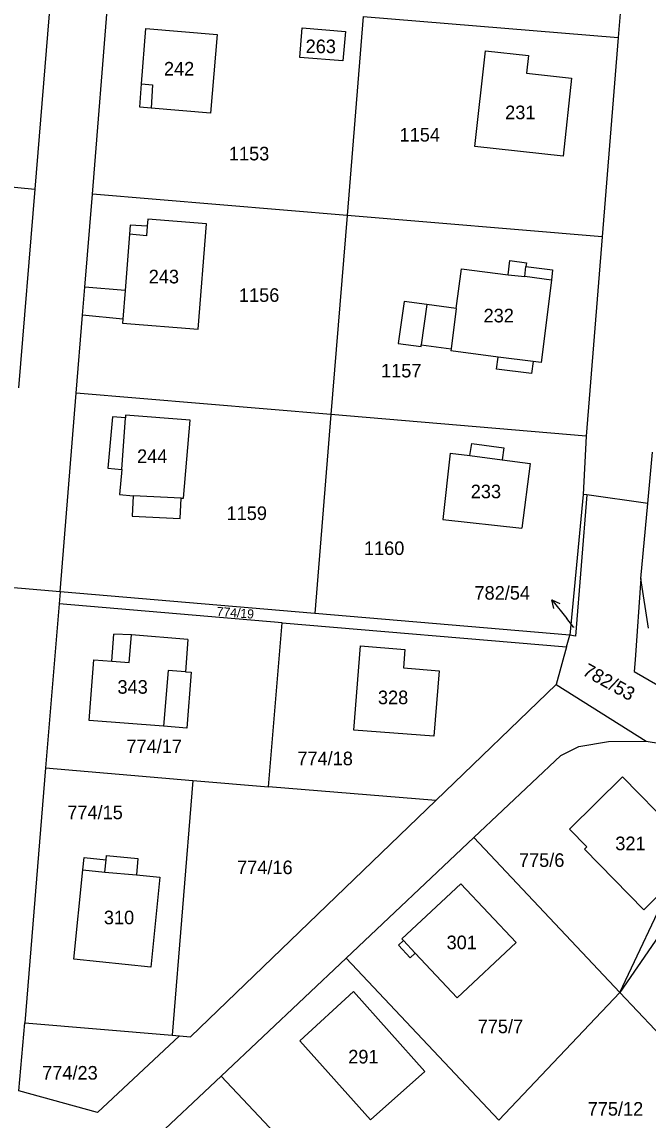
# Model space of a CAD drawing. Extents: x -593358 to -590116, y -1072518 to -1068420.
# Drawn here: x -591943 to -591864.7, y -1070840.2 to -1070702.8 of the extents above; entities that cross this region are included whole.
import ezdxf

# ---------------------------------------------------------------- set-up
doc = ezdxf.new("R2010")
doc.units = 0
for name, color, linetype in [('Parcela KN', 7, 'Continuous'), ('Parcelní číslo', 7, 'Continuous'), ('Parcelní číslo_stavební', 7, 'Continuous'), ('stavby - vnitřní kresba', 7, 'Continuous'), ('Vrstva 16', 7, 'Continuous')]:
    doc.layers.add(name, color=color, linetype=linetype)

msp = doc.modelspace()

# ---------------------------------------------------------------- linework, layer by layer
at = {"layer": 'Parcela KN'}
for p, q in [((-591866.36, -1070679.78), (-591868.38, -1070704.72)), ((-591939.39, -1070698.87), (-591941.43, -1070723.73)), ((-591934.22, -1070724.35), (-591932.21, -1070699.47)), ((-591900.32, -1070702.09), (-591902.34, -1070727)), ((-591900.32, -1070702.09), (-591868.38, -1070704.72)), ((-591928.05, -1070710.51), (-591927.51, -1070703.6)), ((-591927.51, -1070703.6), (-591918.61, -1070704.34)), ((-591918.61, -1070704.34), (-591919.43, -1070714.2)), ((-591908.26, -1070707.25), (-591907.94, -1070703.51)), ((-591907.94, -1070703.51), (-591902.53, -1070703.98)), ((-591902.53, -1070703.98), (-591902.85, -1070707.64)), ((-591868.38, -1070704.72), (-591870.4, -1070729.66)), ((-591902.85, -1070707.64), (-591908.26, -1070707.25)), ((-591886.34, -1070718.35), (-591885.01, -1070706.4)), ((-591885.01, -1070706.4), (-591879.63, -1070707)), ((-591879.63, -1070707), (-591879.88, -1070709.2)), ((-591879.88, -1070709.2), (-591874.23, -1070709.83)), ((-591874.23, -1070709.83), (-591875.29, -1070719.6)), ((-591928.28, -1070713.46), (-591928.05, -1070710.51)), ((-591926.87, -1070713.58), (-591928.28, -1070713.46)), ((-591919.43, -1070714.2), (-591926.87, -1070713.58)), ((-591875.29, -1070719.6), (-591886.34, -1070718.35)), ((-591973.3, -1070720.57), (-591941.43, -1070723.73)), ((-591941.43, -1070723.73), (-591943.47, -1070748.59)), ((-591935.16, -1070735.96), (-591934.22, -1070724.35)), ((-591902.34, -1070727), (-591934.22, -1070724.35)), ((-591927.29, -1070727.47), (-591927.36, -1070728.35)), ((-591919.92, -1070728.06), (-591927.29, -1070727.47)), ((-591920.97, -1070741.24), (-591919.92, -1070728.06)), ((-591902.34, -1070727), (-591904.37, -1070751.91)), ((-591870.4, -1070729.66), (-591902.34, -1070727)), ((-591929.57, -1070729.36), (-591930.13, -1070736.4)), ((-591929.48, -1070728.2), (-591929.57, -1070729.36)), ((-591927.36, -1070728.35), (-591929.48, -1070728.2)), ((-591870.4, -1070729.66), (-591872.42, -1070754.6)), ((-591882.18, -1070734.45), (-591881.95, -1070732.64)), ((-591881.95, -1070732.64), (-591879.89, -1070732.91)), ((-591879.89, -1070732.91), (-591879.95, -1070733.4)), ((-591879.95, -1070733.4), (-591876.6, -1070733.81)), ((-591888.66, -1070738.66), (-591888.02, -1070733.69)), ((-591888.02, -1070733.69), (-591882.18, -1070734.45)), ((-591876.6, -1070733.81), (-591876.76, -1070735.11)), ((-591935.44, -1070739.46), (-591935.16, -1070735.96)), ((-591930.13, -1070736.4), (-591935.16, -1070735.96)), ((-591876.76, -1070735.11), (-591878.06, -1070745.41)), ((-591895.2, -1070737.77), (-591895.92, -1070743.01)), ((-591892.37, -1070738.15), (-591895.2, -1070737.77)), ((-591888.66, -1070738.66), (-591892.37, -1070738.15)), ((-591936.24, -1070749.23), (-591935.44, -1070739.46)), ((-591930.42, -1070739.98), (-591935.44, -1070739.46)), ((-591930.42, -1070739.98), (-591930.46, -1070740.48)), ((-591930.46, -1070740.48), (-591920.97, -1070741.24)), ((-591895.92, -1070743.01), (-591893.08, -1070743.4)), ((-591893.08, -1070743.4), (-591893.05, -1070743.2)), ((-591893.05, -1070743.2), (-591889.32, -1070743.71)), ((-591889.32, -1070743.71), (-591889.35, -1070743.95)), ((-591883.42, -1070744.72), (-591889.35, -1070743.95)), ((-591883.61, -1070746.22), (-591883.42, -1070744.72)), ((-591879.06, -1070745.28), (-591879.26, -1070746.79)), ((-591878.06, -1070745.41), (-591879.06, -1070745.28)), ((-591879.26, -1070746.79), (-591883.61, -1070746.22)), ((-591938.26, -1070774.11), (-591936.24, -1070749.23)), ((-591904.37, -1070751.91), (-591936.24, -1070749.23)), ((-591931.69, -1070752.19), (-591932.28, -1070758.61)), ((-591930.09, -1070752.34), (-591931.69, -1070752.19)), ((-591930.06, -1070752), (-591930.09, -1070752.34)), ((-591921.97, -1070752.62), (-591930.06, -1070752)), ((-591922.81, -1070762.38), (-591921.97, -1070752.62)), ((-591904.37, -1070751.91), (-591906.39, -1070776.81)), ((-591872.42, -1070754.6), (-591904.37, -1070751.91)), ((-591872.42, -1070754.6), (-591872.79, -1070761.92)), ((-591889.43, -1070756.73), (-591890.36, -1070765.05)), ((-591889.43, -1070756.73), (-591886.95, -1070757.05)), ((-591886.95, -1070757.05), (-591886.72, -1070755.55)), ((-591886.72, -1070755.55), (-591882.71, -1070756.07)), ((-591882.71, -1070756.07), (-591882.91, -1070757.58)), ((-591864.7, -1070763.05), (-591864.11, -1070756.64)), ((-591882.91, -1070757.58), (-591879.41, -1070758.03)), ((-591879.41, -1070758.03), (-591880.47, -1070766.14)), ((-591932.28, -1070758.61), (-591930.53, -1070758.77)), ((-591930.53, -1070758.77), (-591930.82, -1070761.91)), ((-591930.82, -1070761.91), (-591929.11, -1070762.07)), ((-591929.11, -1070762.07), (-591929.24, -1070764.62)), ((-591923.21, -1070764.91), (-591923.09, -1070762.37)), ((-591923.09, -1070762.37), (-591922.81, -1070762.38)), ((-591872.79, -1070761.92), (-591874.44, -1070779.54)), ((-591872.34, -1070761.98), (-591873.73, -1070779.64)), ((-591872.34, -1070761.98), (-591872.79, -1070761.92)), ((-591864.7, -1070763.05), (-591872.34, -1070761.98)), ((-591865.58, -1070772.42), (-591864.7, -1070763.05)), ((-591929.24, -1070764.62), (-591923.21, -1070764.91)), ((-591890.36, -1070765.05), (-591880.47, -1070766.14)), ((-591865.58, -1070772.42), (-591866.29, -1070782.63)), ((-591864.62, -1070778.66), (-591865.58, -1070772.42)), ((-591938.26, -1070774.11), (-591945.51, -1070773.47)), ((-591938.26, -1070774.11), (-591938.38, -1070775.61)), ((-591906.39, -1070776.81), (-591938.26, -1070774.11)), ((-591938.38, -1070775.61), (-591940.07, -1070796.14)), ((-591910.48, -1070777.97), (-591938.38, -1070775.61)), ((-591874.44, -1070779.54), (-591906.39, -1070776.81)), ((-591912.17, -1070798.5), (-591910.48, -1070777.97)), ((-591910.48, -1070777.97), (-591874.88, -1070780.98)), ((-591931.8, -1070782.77), (-591931.55, -1070779.38)), ((-591929.32, -1070779.49), (-591931.55, -1070779.38)), ((-591922.27, -1070780.08), (-591929.32, -1070779.49)), ((-591922.27, -1070780.08), (-591922.57, -1070784.11)), ((-591874.88, -1070780.98), (-591874.44, -1070779.54)), ((-591873.73, -1070779.64), (-591874.44, -1070779.54)), ((-591901.49, -1070791.43), (-591900.67, -1070780.84)), ((-591900.67, -1070780.84), (-591895.11, -1070781.3)), ((-591895.11, -1070781.3), (-591895.26, -1070783.61)), ((-591874.88, -1070780.98), (-591876.16, -1070785.71)), ((-591934.63, -1070790.22), (-591934.02, -1070782.61)), ((-591934.02, -1070782.61), (-591931.8, -1070782.77)), ((-591866.29, -1070782.63), (-591866.41, -1070784.05)), ((-591922.57, -1070784.11), (-591921.84, -1070784.17)), ((-591921.84, -1070784.17), (-591922.38, -1070791.16)), ((-591895.26, -1070783.61), (-591890.82, -1070783.97)), ((-591890.82, -1070783.97), (-591891.48, -1070792.15)), ((-591866.41, -1070784.05), (-591837.6, -1070800.72)), ((-591876.16, -1070785.71), (-591891.24, -1070800.23)), ((-591876.16, -1070785.71), (-591864.91, -1070792.8)), ((-591925.3, -1070790.93), (-591934.63, -1070790.22)), ((-591922.38, -1070791.16), (-591925.3, -1070790.93)), ((-591891.48, -1070792.15), (-591901.49, -1070791.43)), ((-591875.56, -1070794.57), (-591873.31, -1070793.45)), ((-591873.31, -1070793.45), (-591869.6, -1070792.82)), ((-591869.6, -1070792.82), (-591864.91, -1070792.8)), ((-591864.91, -1070792.8), (-591859.69, -1070793.62)), ((-591886.47, -1070804.86), (-591875.56, -1070794.57)), ((-591940.07, -1070796.14), (-591942.69, -1070828.05)), ((-591940.07, -1070796.14), (-591921.64, -1070797.7)), ((-591921.64, -1070797.7), (-591924.25, -1070829.59)), ((-591921.64, -1070797.7), (-591912.17, -1070798.5)), ((-591874.5, -1070803.81), (-591867.85, -1070797.27)), ((-591867.85, -1070797.27), (-591859.46, -1070805.82)), ((-591891.24, -1070800.23), (-591912.17, -1070798.5)), ((-591850.34, -1070798.31), (-591868.2, -1070824.23)), ((-591921.93, -1070829.78), (-591891.24, -1070800.23)), ((-591886.47, -1070804.86), (-591902.47, -1070819.95)), ((-591868.2, -1070824.23), (-591886.47, -1070804.86)), ((-591872.34, -1070806.03), (-591874.5, -1070803.81)), ((-591872.6, -1070806.29), (-591872.34, -1070806.03)), ((-591865.19, -1070813.88), (-591872.6, -1070806.29)), ((-591935.42, -1070808.89), (-591935.26, -1070807.35)), ((-591935.26, -1070807.35), (-591932.51, -1070807.63)), ((-591932.51, -1070807.63), (-591932.46, -1070807.1)), ((-591932.46, -1070807.1), (-591928.51, -1070807.45)), ((-591928.51, -1070807.45), (-591928.7, -1070809.53)), ((-591936.56, -1070820.07), (-591935.42, -1070808.89)), ((-591928.7, -1070809.53), (-591925.79, -1070809.81)), ((-591925.79, -1070809.81), (-591926.9, -1070821.06)), ((-591868.2, -1070824.23), (-591861.64, -1070810.41)), ((-591861.64, -1070810.41), (-591865.19, -1070813.88)), ((-591895.49, -1070817.51), (-591888.09, -1070810.63)), ((-591888.09, -1070810.63), (-591881.17, -1070817.99)), ((-591895.89, -1070818.33), (-591895.27, -1070817.74)), ((-591894.42, -1070819.9), (-591895.89, -1070818.33)), ((-591895.27, -1070817.74), (-591895.49, -1070817.51)), ((-591881.17, -1070817.99), (-591888.55, -1070824.92)), ((-591926.9, -1070821.06), (-591936.56, -1070820.07)), ((-591902.47, -1070819.95), (-591918.11, -1070834.69)), ((-591883.33, -1070840.23), (-591902.47, -1070819.95)), ((-591893.8, -1070819.32), (-591894.42, -1070819.9)), ((-591888.55, -1070824.92), (-591893.8, -1070819.32)), ((-591901.55, -1070824.12), (-591908.23, -1070830.29)), ((-591892.61, -1070834.11), (-591901.55, -1070824.12)), ((-591868.2, -1070824.23), (-591883.33, -1070840.23)), ((-591854.24, -1070839.04), (-591868.2, -1070824.23)), ((-591943.42, -1070836.53), (-591942.69, -1070828.05)), ((-591942.69, -1070828.05), (-591924.25, -1070829.59)), ((-591923.31, -1070829.67), (-591933.56, -1070839.27)), ((-591924.25, -1070829.59), (-591923.31, -1070829.67)), ((-591923.31, -1070829.67), (-591921.93, -1070829.78)), ((-591908.23, -1070830.29), (-591899.39, -1070840.17)), ((-591918.11, -1070834.69), (-591933.38, -1070849.09)), ((-591898.97, -1070854.98), (-591918.11, -1070834.69)), ((-591899.39, -1070840.17), (-591892.61, -1070834.11)), ((-591933.56, -1070839.27), (-591943.42, -1070836.53))]:
    msp.add_line(p, q, dxfattribs=at)
at = {"layer": 'stavby - vnitřní kresba'}
for p, q in [((-591928.05, -1070710.51), (-591926.68, -1070710.66)), ((-591926.68, -1070710.66), (-591926.87, -1070713.58)), ((-591927.45, -1070729.53), (-591929.57, -1070729.36)), ((-591927.36, -1070728.35), (-591927.45, -1070729.53)), ((-591880.09, -1070734.65), (-591879.95, -1070733.4)), ((-591882.18, -1070734.45), (-591880.09, -1070734.65)), ((-591876.76, -1070735.11), (-591880.09, -1070734.65)), ((-591930.13, -1070736.4), (-591930.42, -1070739.98)), ((-591892.37, -1070738.15), (-591893.05, -1070743.2)), ((-591888.66, -1070738.66), (-591889.32, -1070743.71)), ((-591879.06, -1070745.28), (-591883.42, -1070744.72)), ((-591930.53, -1070758.77), (-591930.09, -1070752.34)), ((-591886.95, -1070757.05), (-591882.91, -1070757.58)), ((-591923.09, -1070762.37), (-591929.11, -1070762.07)), ((-591929.61, -1070782.93), (-591929.32, -1070779.49)), ((-591931.8, -1070782.77), (-591929.61, -1070782.93)), ((-591924.75, -1070783.95), (-591925.3, -1070790.93)), ((-591922.57, -1070784.11), (-591924.75, -1070783.95)), ((-591932.67, -1070809.17), (-591932.51, -1070807.63)), ((-591935.42, -1070808.89), (-591932.67, -1070809.17)), ((-591932.67, -1070809.17), (-591928.7, -1070809.53)), ((-591895.27, -1070817.74), (-591893.8, -1070819.32))]:
    msp.add_line(p, q, dxfattribs=at)
at = {"layer": 'Vrstva 16'}
for p in [(-591876.696, -1070775.083), (-591873.96, -1070778.55)]:
    msp.add_line(p, (-591874.84, -1070777.44), dxfattribs=at)
msp.add_lwpolyline([(-591876.47, -1070776.178), (-591876.696, -1070775.083), (-591875.684, -1070775.559)], dxfattribs=at)

# ---------------------------------------------------------------- texts
at = {"layer": 'Parcelní číslo'}
for s, height, p in [('1154', 1.7, (-591895.764, -1070717.75)), ('1153', 1.7, (-591917.131, -1070720.11)), ('1156', 1.7, (-591915.874, -1070737.81)), ('1157', 1.7, (-591898.084, -1070747.27)), ('1159', 1.7, (-591917.424, -1070765.11)), ('1160', 1.7, (-591900.224, -1070769.49)), ('782/54', 0.1, (-591874.209, -1070778.55)), ('774/17', 1.7, (-591929.954, -1070794.28)), ('774/18', 1.7, (-591908.564, -1070795.8)), ('774/15', 1.7, (-591937.361, -1070802.55)), ('774/16', 1.7, (-591916.104, -1070809.43)), ('775/6', 1.7, (-591880.82, -1070808.52)), ('775/7', 1.7, (-591885.99, -1070829.33)), ('774/23', 1.7, (-591940.503, -1070835.14)), ('775/12', 1.7, (-591872.215, -1070839.65))]:
    msp.add_text(s, height=height, dxfattribs=at).set_placement(p)
for s, height, rotation, p in [('774/19', 1.14, 355.6922, (-591918.69, -1070777.114)), ('782/53', 1.7, 330.99772, (-591872.995, -1070784.437))]:
    msp.add_text(s, height=height, rotation=rotation, dxfattribs=at).set_placement(p)
at = {"layer": 'Parcelní číslo_stavební'}
for s, p in [('263', (-591907.525, -1070706.69)), ('242', (-591925.261, -1070709.49)), ('231', (-591882.547, -1070714.95)), ('243', (-591927.165, -1070735.5)), ('232', (-591885.249, -1070740.38)), ('244', (-591928.628, -1070757.98)), ('233', (-591886.852, -1070762.39)), ('343', (-591931.078, -1070786.85)), ('328', (-591898.475, -1070788.16)), ('321', (-591868.757, -1070806.43)), ('310', (-591932.78, -1070815.7)), ('301', (-591889.88, -1070818.82)), ('291', (-591902.19, -1070833.12))]:
    msp.add_text(s, height=1.7, dxfattribs=at).set_placement(p)
at = {"layer": 'Vrstva 16'}
msp.add_text('782/54', height=1.7, dxfattribs=at).set_placement((-591886.387, -1070775.08))

doc.saveas('drawing.dxf')
